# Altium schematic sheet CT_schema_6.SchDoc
size 368 x 245 mm
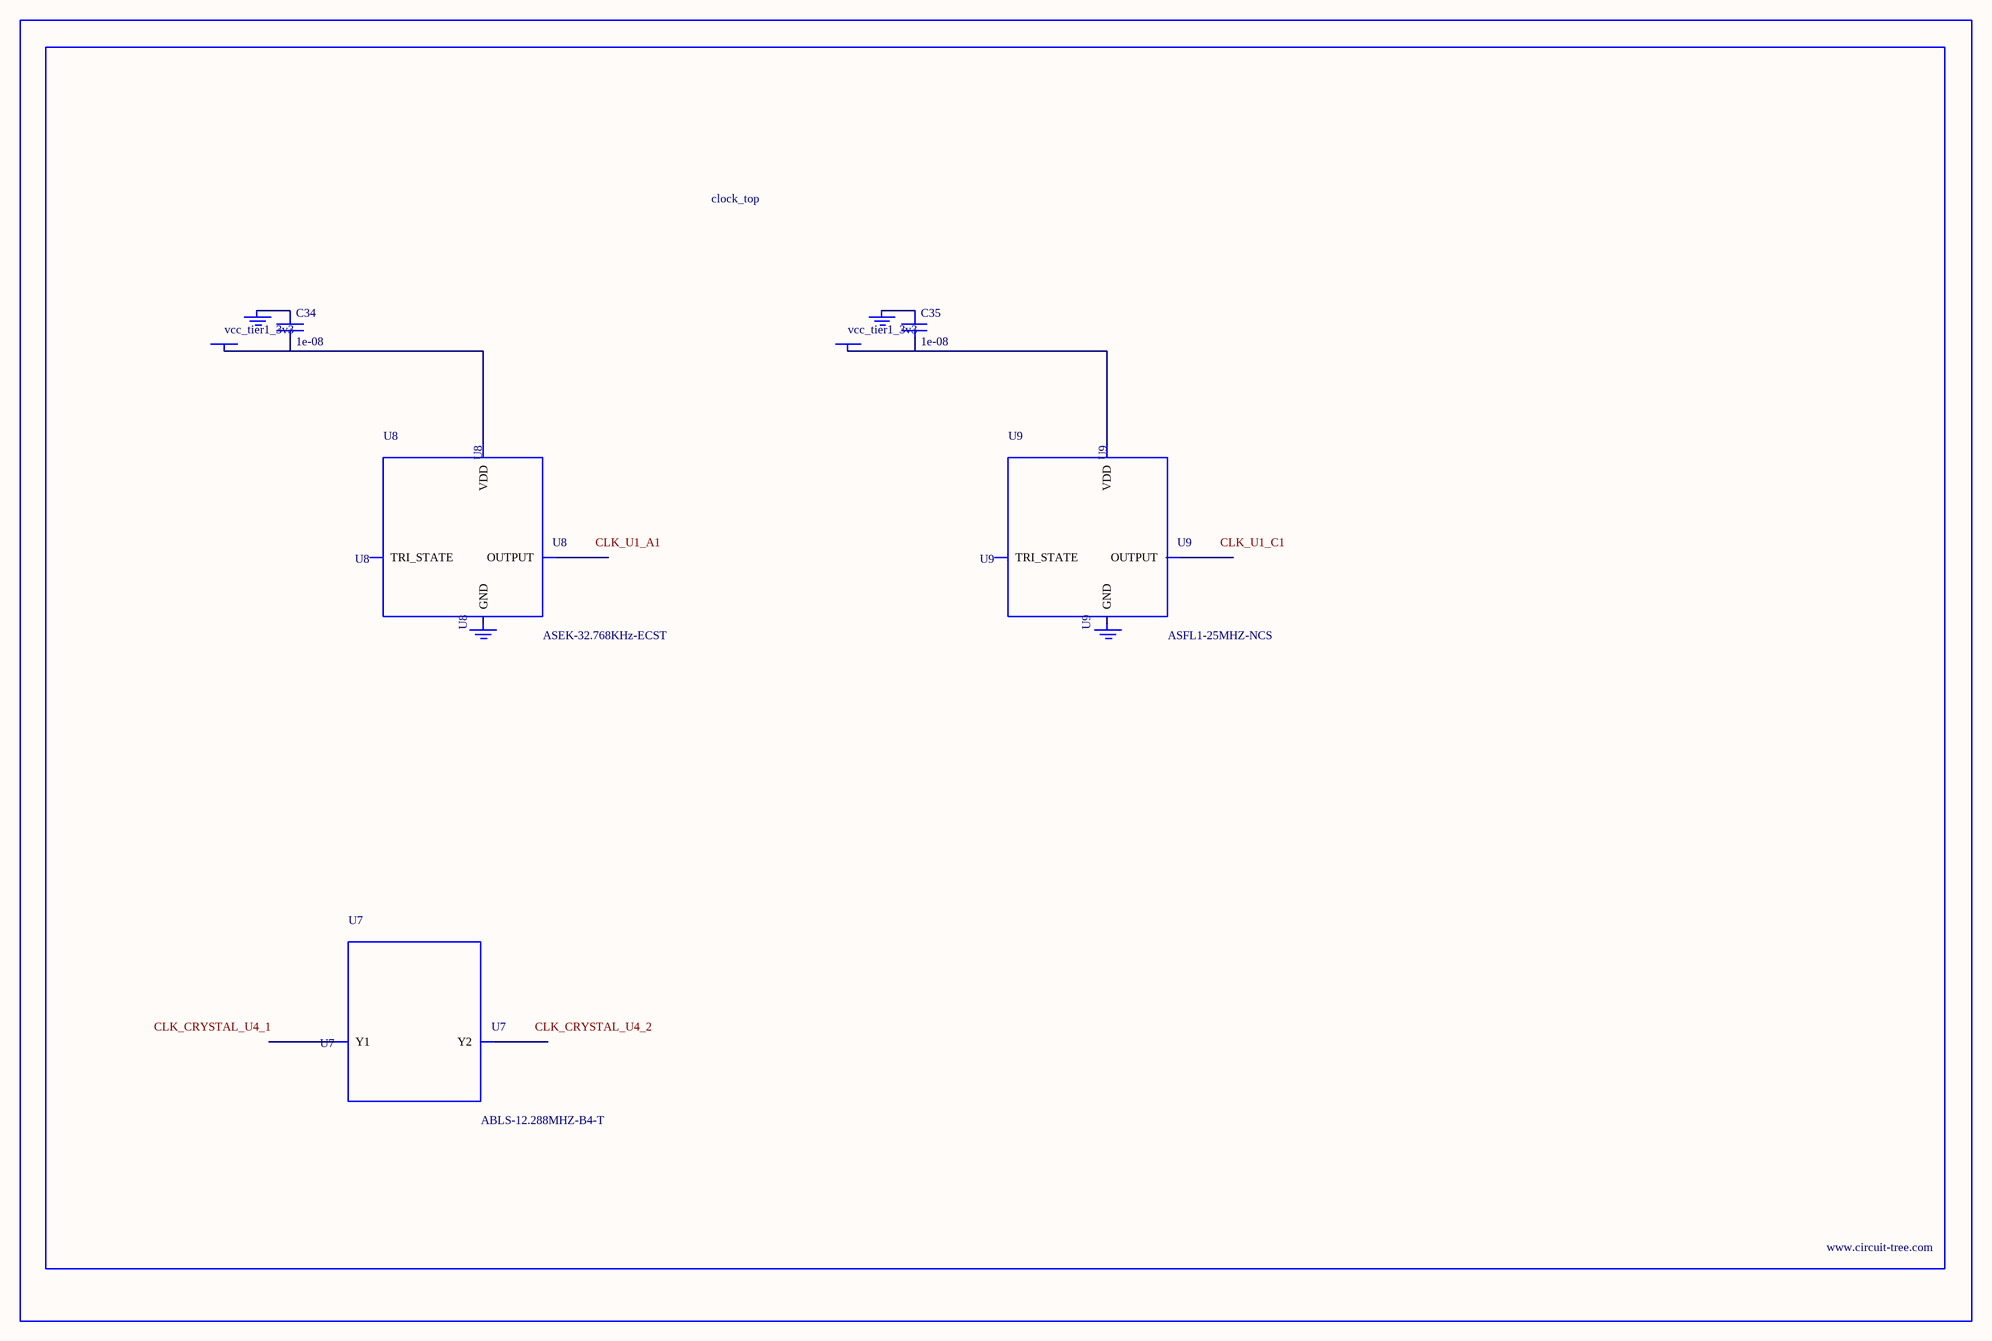
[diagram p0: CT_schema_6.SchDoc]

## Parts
BORDER5  (no value)
C34  1e-08  [C0402]
C35  1e-08  [C0402]
GND_INSTANCE_5_0  (no value)
GND_INSTANCE_5_1  (no value)
GND_INSTANCE_5_2  (no value)
GND_INSTANCE_5_3  (no value)
POWER_INSTANCE_5_0  vcc_tier1_3v3
POWER_INSTANCE_5_1  vcc_tier1_3v3
U7  ABLS-12.288MHZ-B4-T  [ABLS-12.288MHZ-B4-T]
U8  ASEK-32.768KHz-ECST  [ASEK]
U9  ASFL1-25MHZ-NCS  [ASFL1]

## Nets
NetC34_1: C34.1 GND_INSTANCE_5_0.0(GND)
NetC34_2: C34.2 POWER_INSTANCE_5_0.0(PWR) U8.4(VDD)
NetC35_1: C35.1 GND_INSTANCE_5_2.0(GND)
NetC35_2: C35.2 POWER_INSTANCE_5_1.0(PWR) U9.4(VDD)

Not connected (* = marked no-connect by the designer): GND_INSTANCE_5_1 0(GND); GND_INSTANCE_5_3 0(GND); U7 1(Y1) 2(Y2); U8 1(TRI_STATE) 2(GND) 3(OUTPUT); U9 1(TRI_STATE) 2(GND) 3(OUTPUT)

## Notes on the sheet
- Labels drawn without touching a wire or pin: CLK_CRYSTAL_U4_1, CLK_CRYSTAL_U4_2, CLK_U1_A1, CLK_U1_C1

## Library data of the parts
BORDER5 = BORDER_PAGE5
C34 C35 = C0402C103K3RAC
GND_INSTANCE_5_0-GND_INSTANCE_5_3 = GND
POWER_INSTANCE_5_0 POWER_INSTANCE_5_1 = PWR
